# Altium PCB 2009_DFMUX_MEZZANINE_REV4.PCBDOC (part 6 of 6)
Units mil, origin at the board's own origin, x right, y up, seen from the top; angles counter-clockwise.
Board outline 4922.86 x 3627.76 mil, 6 copper layers (Top Layer, Internal Plane 1, Mid-Layer 1, Internal Plane 2, Mid-Layer 2, Bottom Layer); 519 components, 606 nets, 2175 pads, 757 vias.
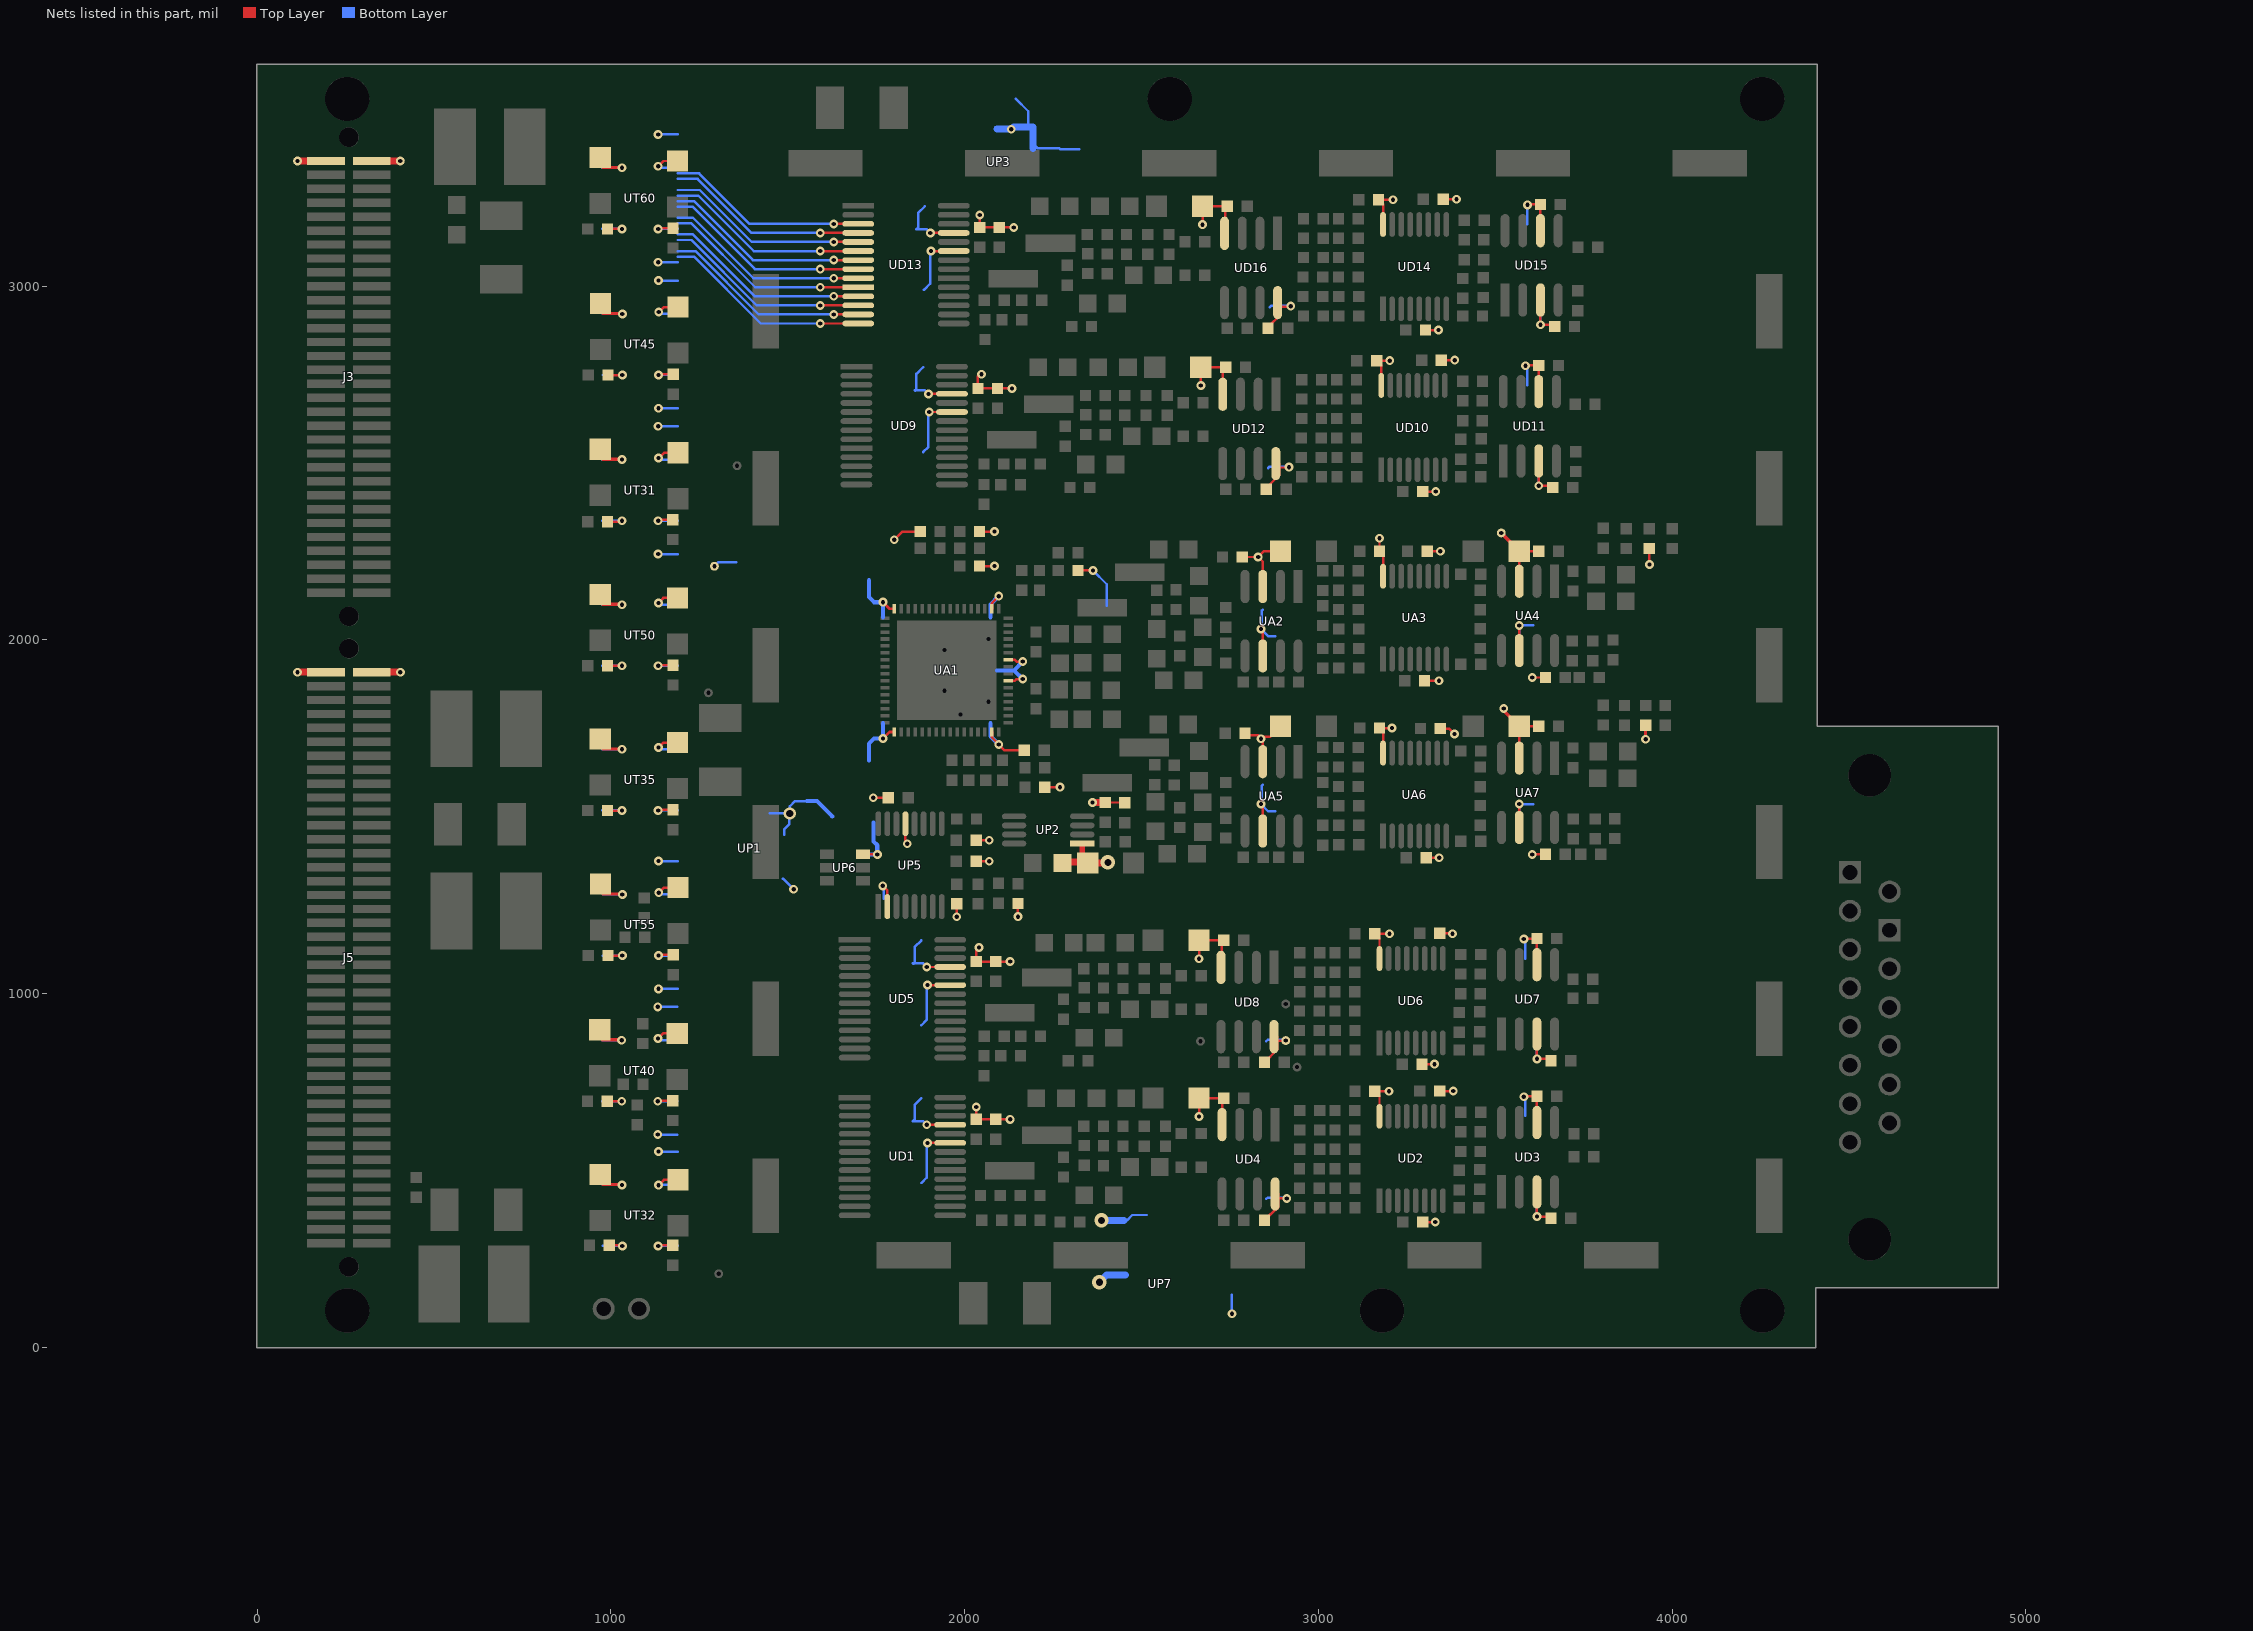
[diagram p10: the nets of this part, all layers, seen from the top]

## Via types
v1: diameter 25, hole 12, Top Layer to Bottom Layer, 692 vias
v2: diameter 40, hole 20, Top Layer to Bottom Layer, 39 vias
v3: diameter 35, hole 20, Top Layer to Bottom Layer, 23 vias
v4: diameter 22, hole 12, Top Layer to Bottom Layer, 3 vias

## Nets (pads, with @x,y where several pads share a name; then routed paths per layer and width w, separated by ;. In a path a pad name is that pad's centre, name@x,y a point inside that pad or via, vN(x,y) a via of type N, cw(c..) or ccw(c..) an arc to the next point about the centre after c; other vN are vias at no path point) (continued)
TRAN4_DATA4: UD13.3 UT60.8 | length 569.6
  Top Layer w7: v1(1630.1,3175.63) UD13.3@1699.03,3175.63
  Bottom Layer w7: UT60.8@1188.63,3318.47 1249.17,3318.47 1392,3175.63 v1(1630.1,3175.63)
TRAN4_DATA5: UD13.4 UT60.9 | length 576.4
  Top Layer w7: v1(1591.77,3150.03) UD13.4@1699.03,3150.03 UD13.4@1697.03,3148.17
  Bottom Layer w7: UT60.9@1188.63,3302.77 1244.87,3302.77 1397.6,3150.03 v1(1591.77,3150.03)
TRAN4_DATA6: UD13.5 UT60.11 | length 571.3
  Top Layer w7: v1(1630.1,3124.43) UD13.5@1699.03,3124.43
  Bottom Layer w7: UT60.11@1188.63,3271.37 1251.27,3271.37 1398.2,3124.43 v1(1630.1,3124.43)
TRAN4_DATA7: UD13.6 UT60.12 | length 575.4
  Top Layer w7: v1(1591.77,3098.83) UD13.6@1699.03,3098.83
  Bottom Layer w7: UT60.12@1188.63,3255.67 1246.97,3255.67 1403.8,3098.83 v1(1591.77,3098.83)
TRAN4_DATA8: UD13.7 UT60.13 | length 579.5
  Top Layer w7: v1(1630.1,3073.23) UD13.7@1699.03,3073.23
  Bottom Layer w7: UT60.13@1188.63,3239.97 1234.67,3239.97 1401.4,3073.23 v1(1630.1,3073.23)
TRAN4_DATA9: UD13.8 UT60.14 | length 583.6
  Top Layer w7: v1(1591.77,3047.63) UD13.8@1699.03,3047.63
  Bottom Layer w7: UT60.14@1188.63,3224.27 1230.37,3224.27 1407,3047.63 v1(1591.77,3047.63)
TRAN4_DATA10: UD13.9 UT60.16 | length 581.2
  Top Layer w7: v1(1630.1,3022.03) UD13.9@1699.03,3022.03
  Bottom Layer w7: UT60.16@1188.63,3192.87 1231.77,3192.87 1402.6,3022.03 v1(1630.1,3022.03)
TRAN4_DATA11: UD13.10 UT60.17 | length 585.3
  Top Layer w7: v1(1591.77,2996.43) UD13.10@1699.03,2996.43
  Bottom Layer w7: UT60.17@1188.63,3177.17 1227.47,3177.17 1408.2,2996.43 v1(1591.77,2996.43)
TRAN4_DATA12: UD13.11 UT60.19 | length 582.9
  Top Layer w7: v1(1630.1,2970.83) UD13.11@1699.03,2970.83
  Bottom Layer w7: UT60.19@1188.63,3145.77 1231.87,3145.77 1406.8,2970.83 v1(1630.1,2970.83)
TRAN4_DATA13: UD13.12 UT60.20 | length 587
  Top Layer w7: v1(1591.77,2945.23) UD13.12@1699.03,2945.23
  Bottom Layer w7: UT60.20@1188.63,3130.07 1227.57,3130.07 1412.4,2945.23 v1(1591.77,2945.23)
TRAN4_DATA14: UD13.13 UT60.22 | length 584.6
  Top Layer w7: v1(1630.1,2919.63) UD13.13@1699.03,2919.63
  Bottom Layer w7: UT60.22@1188.63,3098.67 1238.97,3098.67 1418,2919.63 v1(1630.1,2919.63)
TRAN4_DATA15: UD13.14 UT60.23 | length 588.7
  Top Layer w7: v1(1591.77,2894.03) UD13.14@1699.03,2894.03
  Bottom Layer w7: UT60.23@1188.63,3082.97 1234.67,3082.97 1423.6,2894.03 v1(1591.77,2894.03)
VCC3VP: CA4.1 CA15.1 CA18.1 CA27.1 CP8.2 CP10.1 CP19.2 DP2.1 RA9.2 RA44.2 RP9.1 RP11.2 RP31.1 UA1.7 UA1.10 UA1.18 UA1.63 UP2.1 UP5.2 | length 1203.7
  Top Layer w7: v1(1768.63,1304.37) 1781.53,1291.47 UP5.2@1781.53,1245.8 ; v1(1977.63,1217) RP31.1@1977.63,1253.37 ; v1(2096.5,1703.91) 2113.05,1687.37 CA27.1@2168.63,1687.37 ; UA1.7@2123.35,1884.11 2141.97,1884.11 2146.77,1888.91 v1(2164.27,1888.91) ; UA1.10@2123.35,1943.17 2141.97,1943.17 2146.77,1938.37 v1(2164.27,1938.37) ; RA44.2@2226.77,1583.37 v1(2269.27,1583.37) ; RP11.2@2276.63,1369 RP11.2@2279.63,1372 ; RA9.2@2320.27,2195.87 v1(2362.77,2195.87) ; CP10.1@2332.63,1371 CP10.1@2347.63,1369 CP10.1@2344.63,1372 ; CP8.2@2397.63,1540 2451.63,1540 RP9.1@2452.63,1539 ; v2(2404.63,1371) v2@2406.63,1369
  Top Layer w8: UA1.63@2077.09,1739.43 2077.09,1723.32 v1(2096.5,1703.91) ; UA1.18@2077.09,2087.85 2077.09,2103.95 v1(2096.5,2123.37)
  Top Layer w15: CP10.1@2332.63,1372 UP2.1@2332.63,1424
  Top Layer w20: RP11.2@2279.63,1372 CP10.1@2332.63,1372 ; CP10.1@2332.63,1371 CP10.1@2332.63,1372 ; CP10.1@2344.63,1372 CP10.1@2332.63,1372 ; CP10.1@2347.63,1369 v2@2406.63,1369 ; v1(2361.63,1540) CP8.2@2397.63,1540
  Bottom Layer w7: v1(1768.63,1304.37) 1771.63,1301.37 CP19.2@1771.63,1268.37 ; v1(2362.77,2195.87) 2401.63,2157 ; 2401.63,2157 DP2.1@2401.63,2096 2401.63,2157
  Bottom Layer w12: CA18.1@2073,1763.91 2073,1727.41 v1(2096.5,1703.91) ; CA4.1@2073,2063.37 2073,2099.87 v1(2096.5,2123.37) ; CA15.1@2091.77,1913.37 2139.81,1913.37 v1(2164.27,1888.91) ; 2139.27,1913.37 v1(2164.27,1938.37)
VCC5VN: CA16.1 CA17.2 CA32.1 CA34.2 CA38.1 CA39.2 CA42.1 CA43.2 CD1.1 CD2.2 CD8.1 CD9.1 CD14.2 CD15.1 CD21.1 CD22.2 CD28.1 CD29.1 CD34.2 CD35.1 CD41.1 CD42.2 CD48.1 CD49.1 CD54.2 CD55.1 CD61.1 CD62.2 CD68.1 CD69.1 CD74.2 CD75.1 CD83.1 CD85.1 CD87.1 CD89.1 CD91.2 CD93.2 CD95.2 CD97.2 CP16.2 DP4.2 RP20.2 RP22.1 UA2.6 UA4.6 UA5.6 UA7.6 UD1.23 UD3.6 UD4.4 UD5.23 UD7.6 UD8.4 UD9.23 UD11.6 UD12.4 UD13.23 UD15.6 UD16.4 UP7.3 | length 4074.5
  Top Layer w7: v1(1895.03,577.83) UD1.23@1959.03,577.83 ; v1(1895.03,1023.83) UD5.23@1959.03,1023.83 ; v1(1905.03,3098.83) UD13.23@1969.03,3098.83 ; RP22.1@2032.63,1433.37 v1(2069.63,1433.37) ; v1(2047.63,2750.37) 2042.57,2750.37 2037.63,2745.43 CD48.1@2037.63,2710.43 CD49.1@2092.63,2710.43 v1(2133.63,2710.43) ; v1(2128.63,644.43) CD9.1@2087.63,644.43 CD8.1@2032.63,644.43 ; v1(2128.63,1090.43) CD29.1@2087.63,1090.43 CD28.1@2032.63,1090.43 2032.63,1125.43 v1@2037.57,1130.37 ; v1(2138.63,3165.43) CD69.1@2097.63,3165.43 CD68.1@2042.63,3165.43 ; v1(2662.63,652.43) CD2.2@2662.63,704.43 CD1.1@2732.63,704.43 2728.63,700.43 2728.63,630.43 UD4.4@2727.63,629.43 ; v1(2662.63,1098.43) CD22.2@2662.63,1150.43 CD21.1@2732.63,1150.43 2726.63,1144.43 2726.63,1076 UD8.4@2724.63,1074 ; v1(2667.63,2718.43) CD42.2@2667.63,2770.43 CD41.1@2737.63,2770.43 2729.63,2762.43 UD12.4@2729.63,2694 ; v1(2672.63,3173.43) CD62.2@2672.63,3225.43 CD61.1@2742.63,3225.43 2736.63,3219.43 2736.63,3151 UD16.4@2734.63,3149 ; v1(2837.63,1535.43) 2839.63,1535.43 2842.63,1532.43 UA5.6@2842.63,1459.43 ; v1(2837.63,2030.43) 2839.63,2030.43 2842.63,2027.43 UA2.6@2842.63,1954.43 ; UA7.6@3567.63,1465.43 UA7.6@3567.63,1469.43 v1(3567.63,1535.43) v1@3567.63,1540.43 ; v1(3580.63,708.43) 3580.63,709.43 CD83.1@3617.63,709.43 UD3.6@3617.63,635.43 ; v1(3580.63,1154.43) 3580.63,1155.43 CD85.1@3617.63,1155.43 UD7.6@3617.63,1081.43 ; v1(3585.63,2774.43) 3585.63,2775.43 CD87.1@3622.63,2775.43 UD11.6@3622.63,2701.43 ; v1(3590.63,3229.43) 3590.63,3230.43 CD89.1@3627.63,3230.43 UD15.6@3627.63,3156.43 ; CD8.1@2032.63,644.43 v1(2032.63,679.43) CD8.1@2032.63,644.43 ; v1@2037.57,1130.37 v1(2040.63,1130.37) v1@2037.57,1130.37 ; CD68.1@2042.63,3165.43 v1(2042.63,3200.43) CD68.1@2042.63,3165.43 ; v1(1900.03,2643.83) UD9.23@1964.03,2643.83 v1(1900.03,2643.83) ; UA4.6@3567.63,1969.43 v1(3567.63,2040.43) UA4.6@3567.63,1969.43
  Bottom Layer w7: CD14.2@1877.63,464.43 1892.63,479.43 CD15.1@1892.63,534.43 1892.63,575.43 v1(1895.03,577.83) ; CD34.2@1877.63,910.43 1892.63,925.43 CD35.1@1892.63,980.43 1892.63,1021.43 v1(1895.03,1023.83) ; CD54.2@1882.63,2530.43 1897.63,2545.43 CD55.1@1897.63,2600.43 1897.63,2641.43 v1(1900.03,2643.83) ; CD74.2@1884.63,2989 1902.63,3007 CD75.1@1902.63,3055.43 1902.63,3096.43 v1(1905.03,3098.83) ; CP16.2@2449.63,359 2458.63,359 2473.63,374 RP20.2@2514.63,374 ; v1(2755.63,95) DP4.2@2755.63,149 ; CA34.2@2842.63,1590.43 2839.63,1587.43 2839.63,1537.43 v1(2837.63,1535.43) ; CA17.2@2842.63,2085.43 2839.63,2082.43 2839.63,2032.43 v1(2837.63,2030.43) ; CA32.1@2877.63,1515.43 2857.63,1515.43 ; CA16.1@2877.63,2010.43 2857.63,2010.43 ; CA43.2@3567.63,1465.43 v1(3567.63,1535.43) CA42.1@3606.63,1535.43 ; CA39.2@3567.63,1970.43 v1(3567.63,2040.43) CA38.1@3606.63,2040.43 ; v1@3580.63,709.43 v1(3580.63,708.43) 3579.63,708.43 3579.63,704 3584.63,699 CD91.2@3584.63,654 ; v1@3580.63,1155.43 v1(3580.63,1154.43) 3579.63,1154.43 3579.63,1149 3584.63,1144 CD93.2@3584.63,1099 ; v1@3585.63,2775.43 v1(3585.63,2774.43) 3589.2,2774.43 3589.63,2774 CD95.2@3589.63,2719 ; CD97.2@3589.63,3174 3589.63,3229.43 v1(3590.63,3229.43) ; v1(2837.63,1535.43) 2857.63,1515.43 ; v1(2837.63,1535.43) 2857.63,1515.43 ; v1(2837.63,2030.43) 2857.63,2010.43 ; v1(2837.63,2030.43) 2857.63,2010.43
  Bottom Layer w20: v2(2380.63,184) 2400.63,204 UP7.3@2454.63,204 ; v2(2386.63,359) CP16.2@2449.63,359
VCC5VP: CA3.1 CA5.1 CA23.1 CA24.1 CA36.1 CA37.1 CA40.1 CA41.1 CD3.1 CD4.2 CD6.1 CD19.1 CD20.1 CD23.1 CD24.2 CD26.1 CD39.1 CD40.1 CD43.1 CD44.2 CD46.1 CD59.1 CD60.1 CD63.1 CD64.2 CD66.1 CD79.1 CD80.1 CD81.1 CD82.1 CD84.1 CD86.1 CD88.1 CD90.1 CD92.1 CD94.1 CD96.1 CD98.1 CP11.1 CP14.1 DP3.1 pad.1@2907.63,867 pad.1@3517,2302 RA10.1 RA30.1 RA31.1 RA55.1 RD1.1 RD29.1 RD31.1 RD59.1 RD61.1 RD89.1 RD91.1 RD119.1 RP14.1 RP16.2 RP21.1 RP25.2 RP30.1 RP32.2 RP54.2 RP57.2 UA2.3 UA3.16 UA4.3 UA5.3 UA6.16 UA7.3 UD1.25 UD2.16 UD3.3 UD4.8 UD5.25 UD6.16 UD7.3 UD8.8 UD9.25 UD10.16 UD11.3 UD12.8 UD13.25 UD14.16 UD15.3 UD16.8 UP3.1 | length 6111.9
  Top Layer w7: v1(1893.03,629.03) UD1.25@1959.03,629.03 ; v1(1898.03,2695.03) UD9.25@1964.03,2695.03 ; v1(1903.03,3150.03) UD13.25@1969.03,3150.03 ; RP21.1@2032.63,1374 v1(2069.63,1374) ; CA5.1@2784.63,2234 v1(2829.63,2234) ; CA24.1@2792.63,1735.43 2797.63,1730.43 2828.63,1730.43 v1@2837.63,1721.43 ; v1(2837.63,1720.43) v1@2837.63,1721.43 ; UA2.3@2842.63,2150.43 2842.63,2221 v1(2829.63,2234) ; CD40.1@2847.63,805.43 2883.63,841.43 UD8.8@2883.63,868 ; CD80.1@2857.63,2880.43 2857.63,2884 2893.63,2920 UD16.8@2893.63,2943 ; CA23.1@2892.63,1755.43 2862.63,1725.43 2839.63,1725.43 2842.63,1722.43 v1@2842.63,1720.43 ; CA3.1@2892.63,2250.43 2846.07,2250.43 v1(2829.63,2234) ; pad.1@2907.63,867 2884.63,867 UD8.8@2883.63,868 ; v1(2916.63,2488) 2915.63,2487 2889.63,2487 UD12.8@2888.63,2488 ; v1(2921.63,2943) 2920.63,2942 2894.63,2942 UD16.8@2893.63,2943 ; UD2.16@3172.63,653.02 3172.63,711 CD6.1@3159.63,724 ; UD6.16@3172.63,1099.02 3172.63,1156 CD26.1@3159.63,1169 v1(3200.63,1169) ; UD10.16@3177.63,2719.02 3177.63,2776 CD46.1@3164.63,2789 ; UA6.16@3182.63,1679.68 3182.63,1740.43 CD82.1@3172.63,1750.43 v1(3208.2,1750.43) ; UA3.16@3182.63,2179.68 3182.63,2240.43 CD81.1@3172.63,2250.43 ; UD14.16@3182.63,3174.02 3182.63,3231 CD66.1@3169.63,3244 v1(3210.63,3244) ; RD29.1@3294.63,354 v1(3330.2,354) ; RA30.1@3299.63,1884 v1(3340.63,1884) ; v1@3340.63,1384.57 v1(3341.2,1384) ; RD91.1@3352.63,3245.43 v1(3390.2,3245.43) v1@3388.63,3247 ; UA7.3@3567.63,1665.43 CA40.1@3567.63,1755.43 CA41.1@3622.63,1755.43 ; UA4.3@3567.63,2165.43 CA36.1@3567.63,2250.43 CA37.1@3622.63,2250.43 ; UD3.3@3617.63,439.43 v1(3617.63,369.43) 3652.63,369.43 CD84.1@3657.63,364.43 ; UD7.3@3617.63,885.43 v1(3617.63,815.43) 3652.63,815.43 CD86.1@3657.63,810.43 ; UD11.3@3622.63,2505.43 v1(3622.63,2435.43) 3657.63,2435.43 CD88.1@3662.63,2430.43 ; UD15.3@3627.63,2960.43 v1(3627.63,2890.43) 3662.63,2890.43 CD90.1@3667.63,2885.43 ; v1@2837.63,1721.43 2837.63,1722.43 2839.63,1720.43 v1@2842.63,1720.43 ; v1@2842.63,1720.43 UA5.3@2842.63,1655.43 v1@2842.63,1720.43 ; CD20.1@2847.63,359.43 2883.63,395.43 UD4.8@2883.63,426.43 ; CD20.1@2847.63,359.43 UD4.8@2886.63,396.87 ; CD20.1@2847.63,359.43 UD4.8@2886.63,396.87 ; CD60.1@2852.63,2429 2888.63,2465 UD12.8@2888.63,2488 ; CD60.1@2852.63,2429 CD60.1@2852.63,2425.43 CD60.1@2852.63,2429 ; UD8.8@2874.63,878 UD8.8@2881.2,878 ; UD8.8@2874.63,878 UD8.8@2881.2,878 ; UD8.8@2874.63,878 2875.63,877 2875.63,876 UD8.8@2883.63,868 ; UD4.8@2877.63,433.43 2878.63,432.43 UD4.8@2878.63,431.43 ; UD4.8@2877.63,433.43 UD4.8@2884.2,433.43 ; UD4.8@2877.63,433.43 UD4.8@2884.2,433.43 ; UD4.8@2877.63,433.43 2877.63,432.43 UD4.8@2878.63,431.43 ; UD4.8@2878.63,431.43 UD4.8@2883.63,426.43 ; UD12.8@2879.63,2498 UD12.8@2880.63,2497 ; UD12.8@2879.63,2498 2879.63,2497 UD12.8@2880.63,2496 ; UD12.8@2879.63,2498 UD12.8@2880.63,2497 ; UD12.8@2879.63,2498 2886.2,2498 2887.63,2499.43 2887.63,2498.43 2888.63,2497.43 UD12.8@2888.63,2489 ; UD12.8@2880.63,2496 UD12.8@2880.63,2497 ; UD12.8@2880.63,2496 UD12.8@2888.63,2488 ; UD12.8@2880.63,2497 UD12.8@2888.63,2489 ; UD8.8@2881.2,878 UD8.8@2882.63,879.43 ; UD8.8@2882.63,879.43 2883.63,878.43 UD8.8@2883.63,877.43 ; UD8.8@2882.63,879.43 2882.63,878.43 UD8.8@2883.63,877.43 ; UD4.8@2883.63,426.43 UD4.8@2886.63,423.43 ; UD8.8@2883.63,868 UD8.8@2883.63,877.43 ; UD4.8@2884.2,433.43 2885.63,434.87 2886.63,433.87 UD4.8@2886.63,423.43 ; UD16.8@2884.63,2953 2884.63,2952 UD16.8@2893.63,2943 ; UD16.8@2884.63,2953 UD16.8@2893.63,2944 ; UD16.8@2884.63,2953 2891.2,2953 2892.63,2954.43 2892.63,2953.43 2893.63,2952.43 UD16.8@2893.63,2944 ; UD16.8@2884.63,2953 UD16.8@2893.63,2944 ; UD4.8@2886.63,396.87 UD4.8@2886.63,421 ; UD4.8@2886.63,421 UD4.8@2886.63,423.43 ; UD4.8@2886.63,421 2907.63,421 UD4.8@2886.63,421 ; UD12.8@2888.63,2488 UD12.8@2888.63,2489 ; UD16.8@2893.63,2943 UD16.8@2893.63,2944 ; CD6.1@3159.63,724 v1(3199.63,724) CD6.1@3159.63,724 ; CD46.1@3164.63,2789 v1(3201.63,2789) CD46.1@3164.63,2789 ; CD81.1@3172.63,2250.43 v1(3172.63,2287) CD81.1@3172.63,2250.43 ; RD59.1@3292.63,800.43 v1(3328.2,800.43) ; RD59.1@3292.63,800.43 v1(3328.2,800.43) ; RD59.1@3292.63,800.43 v1(3328.2,800.43) ; v1(3341.2,1384) RA55.1@3304.63,1384 v1(3341.2,1384) ; 3369.63,1749 v1(3384.63,1734) 3369.63,1749 ; 3369.63,1749 RA31.1@3344.63,1749 3369.63,1749 ; v1@3377.2,1170.43 v1(3378.63,1169) v1@3377.2,1170.43 ; v1@3377.2,1170.43 RD31.1@3342.63,1170.43 v1@3377.2,1170.43 ; v1(3385.2,2790.43) 3383.63,2792 v1(3385.2,2790.43) ; v1(3385.2,2790.43) RD61.1@3347.63,2790.43 v1(3385.2,2790.43) ; v1(1893.03,1075.03) UD5.25@1959.03,1075.03 v1(1893.03,1075.03) ; v1(2150.63,1217.37) RP30.1@2150.63,1254.37 v1(2150.63,1217.37) ; RD89.1@3294.63,2419 v1(3331.63,2419) RD89.1@3294.63,2419 ; RD119.1@3302.63,2875.43 v1(3339.63,2875.43) RD119.1@3302.63,2875.43 ; RA10.1@3307.63,2250.43 v1(3344.63,2250.43) RA10.1@3307.63,2250.43 ; RD1.1@3342.63,724.43 v1(3381.2,724.43) RD1.1@3342.63,724.43 ; v1(3604.63,1393.37) RP32.2@3641.63,1393.37 v1(3604.63,1393.37) ; v1(3604.63,1893.37) RP25.2@3641.63,1893.37 v1(3604.63,1893.37)
  Top Layer w8: v1(3925,1719) RP57.2@3925,1758 ; RP54.2@3935,2258 3935,2214 v1(3936,2213) v1@3936,2215
  Top Layer w10: pad.1@3517,2302 3567.63,2251.37 CA36.1@3567.63,2250.43 ; v1(3524,1806) 3524,1799.07 CA40.1@3567.63,1755.43
  Bottom Layer w7: CD3.1@1877.63,704.43 1858.63,685.43 1858.63,644.37 CD4.2@1853.63,639.37 1858.57,639.37 1858.63,639.43 1882.63,639.43 v1(1893.03,629.03) ; CD23.1@1877.63,1150.43 1858.63,1131.43 1858.63,1087 1857,1085.37 ; CD43.1@1882.63,2770.43 1863.63,2751.43 1863.63,2707 1862,2705.37 ; CD63.1@1887.63,3225.43 1868.63,3206.43 1868.63,3165.37 CD64.2@1863.63,3160.37 1868.57,3160.37 1868.63,3160.43 1892.63,3160.43 v1(1903.03,3150.03) ; v1(1893.03,1075.03) 1882.63,1085.43 1858.63,1085.43 1858.57,1085.37 1857,1085.37 ; v1(1898.03,2695.03) 1887.7,2705.37 1862,2705.37 ; RP16.2@2086.63,3449 2091.63,3444 ; v1(2131.63,3443) 2132.63,3444 v1@2137.63,3449 ; DP3.1@2144.63,3529 2179.63,3494 2179.63,3449 ; 2192.63,3404 2207.63,3389 CP11.1@2267.63,3389 2269.63,3387 RP14.1@2324.63,3387 ; CD19.1@2852.63,419.43 2856.63,423.43 2910.63,423.43 v1(2910.63,421) v1@2907.63,421 ; CD59.1@2857.63,2485.43 2861.63,2489.43 2915.63,2489.43 v1@2916.63,2488.43 ; CD79.1@2862.63,2940.43 2866.63,2944.43 2920.63,2944.43 v1@2921.63,2943.43 ; CD24.2@1855.63,1084 1855,1084 1853.63,1085.37 1857,1085.37 ; CD24.2@1855.63,1084 1857,1085.37 ; CD24.2@1855.63,1084 1857,1085.37 ; CD44.2@1860.63,2704 1860,2704 1858.63,2705.37 1862,2705.37 ; CD44.2@1860.63,2704 1862,2705.37 ; CD44.2@1860.63,2704 1862,2705.37 ; 2856.63,869.43 2910.63,869.43 pad.1@2910.63,867 ; 2856.63,869.43 CD39.1@2852.63,865.43 2856.63,869.43 ; pad.1@2910.63,867 pad.1@2907.63,867 pad.1@2910.63,867 ; v1@2916.63,2488.43 v1(2916.63,2488) v1@2916.63,2488.43 ; v1@2921.63,2943.43 v1(2921.63,2943) v1@2921.63,2943.43 ; v1(3617.63,369.43) CD92.1@3617.63,434.43 v1(3617.63,369.43) ; v1(3617.63,815.43) CD94.1@3617.63,880.43 v1(3617.63,815.43) ; v1(3622.63,2435.43) CD96.1@3622.63,2500.43 v1(3622.63,2435.43) ; v1(3627.63,2890.43) CD98.1@3627.63,2955.43 v1(3627.63,2890.43)
  Bottom Layer w20: 2091.63,3444 v1@2132.63,3444 ; v1@2137.63,3449 2179.63,3449 CP14.1@2192.63,3449 2192.63,3404 ; 2192.63,3404 UP3.1@2192.63,3389 2192.63,3404
VDD3V: CA7.2 CA25.1 CA44.1 CA45.1 CP4.2 CP7.1 CP21.1 CP22.2 CT27.1 CT28.2 CT31.1 CT32.2 CT33.1 CT34.2 CT37.1 CT38.2 CT41.1 CT42.2 CT45.1 CT46.2 CT49.1 CT50.2 CT53.1 CT54.2 DP1.1 pad.1@1292.63,2208 RA2.1 RA4.1 RA6.1 RA56.1 RP5.1 RP7.2 UA1.32 UA1.49 UP1.1 UP5.13 UP6.3 UT31.1 UT31.7 UT31.18 UT31.24 UT32.1 UT32.7 UT32.18 UT35.7 UT35.18 UT40.1 UT40.7 UT40.18 UT40.24 UT45.1 UT45.7 UT45.18 UT45.24 UT50.7 UT50.18 UT55.1 UT55.7 UT55.18 UT55.24 UT60.1 UT60.7 UT60.18 UT60.24 | length 5036.1
  Top Layer w7: v1@1132.63,872.37 1147.63,887.37 ; v1(1133.43,873.17) 1147.63,887.37 ; v1@1133.63,695.37 v1@1135.63,697.37 ; v1@1133.63,1694.37 1148.63,1709.37 ; v1(1133.63,3161.47) 1135.53,3163.37 CT54.2@1175.63,3163.37 ; v1@1134.43,3339.17 1148.63,3353.37 ; v1@1134.63,1517.37 v1@1136.63,1519.37 ; v1(1134.63,2748.47) 1136.53,2750.37 CT42.2@1176.63,2750.37 ; v1(1135.43,1285.17) 1149.63,1299.37 ; v1(1135.43,2926.17) 1149.63,2940.37 ; v1@1135.63,1107.37 v1@1137.63,1109.37 ; CT49.1@1189.63,1299.37 1149.63,1299.37 ; CT41.1@1189.63,2940.37 1149.63,2940.37 ; v1(1741.77,1553.37) RA56.1@1784.27,1553.37 ; v1(1801.13,2282.93) 1823.73,2305.87 RA6.1@1874.27,2305.87 ; UP5.13@1832.7,1480.05 1832.7,1428.3 v1(1837.63,1423.37) ; RA2.1@2041.77,2208.37 v1(2084.27,2208.37) ; RA4.1@2041.77,2305.87 v1(2084.27,2305.87) ; v1@1135.63,288.37 v1(1133.63,286.37) v1@1135.63,288.37 ; v1@1135.63,288.37 CT32.2@1174.63,288.37 v1@1135.63,288.37 ; v1@1135.63,697.37 CT38.2@1174.63,697.37 v1@1135.63,697.37 ; v1@1136.63,1519.37 CT34.2@1175.63,1519.37 v1@1136.63,1519.37 ; v1@1136.63,1928.37 CT46.2@1175.63,1928.37 v1@1136.63,1928.37 ; v1@1136.63,1928.37 1134.63,1926.37 v1@1136.63,1928.37 ; v1@1136.63,2339.37 1133.63,2336.37 v1@1136.63,2339.37 ; v1@1136.63,2339.37 CT28.2@1174.63,2339.37 v1@1136.63,2339.37 ; v1@1137.63,1109.37 CT50.2@1176.63,1109.37 v1@1137.63,1109.37 ; 1147.63,887.37 CT37.1@1187.63,887.37 1147.63,887.37 ; 1148.63,1709.37 v1(1134.43,1695.17) 1148.63,1709.37 ; 1148.63,1709.37 CT33.1@1188.63,1709.37 1148.63,1709.37 ; 1148.63,2118.37 v1(1134.43,2104.17) 1148.63,2118.37 ; 1148.63,2118.37 CT45.1@1188.63,2118.37 1148.63,2118.37 ; 1148.63,3353.37 CT53.1@1188.63,3353.37 1148.63,3353.37 ; 1149.63,473.37 CT31.1@1189.63,473.37 1149.63,473.37 ; 1149.63,473.37 v1(1134.63,458.37) 1149.63,473.37 ; 1149.63,1299.37 1134.63,1284.37 1149.63,1299.37 ; 1149.63,2940.37 1134.63,2925.37 1149.63,2940.37 ; 1150.63,2528.37 CT27.1@1189.63,2528.37 1150.63,2528.37 ; 1150.63,2528.37 1132.63,2510.37 1150.63,2528.37 ; UP6.3@1712.63,1393.37 v1(1753.27,1393.37) UP6.3@1712.63,1393.37
  Top Layer w8: v1(1769.27,1720.87) 1787.83,1739.43 UA1.49@1801.5,1739.43 ; v1(1769.27,2106.41) 1787.83,2087.85 UA1.32@1801.5,2087.85
  Bottom Layer w7: v1@1130.03,962.37 v1(1132.63,962.37) ; v1@1131.03,3428.37 v1(1133.63,3428.37) ; v1@1132.03,1374.37 v1(1134.63,1374.37) ; v1@1132.03,3015.37 v1(1134.63,3015.37) ; v1(1132.63,601.27) UT40.24@1187.63,601.27 ; v1@1132.63,2510.37 1133.83,2509.17 UT31.7@1188.63,2509.17 ; v1(1133.43,873.17) 1138.47,868.17 UT40.7@1187.63,868.17 ; v1(1133.63,286.37) 1133.73,286.47 UT32.18@1189.63,286.47 ; v1@1133.63,695.37 1133.73,695.47 UT40.18@1187.63,695.47 ; v1@1133.63,2103.37 v1(1134.43,2104.17) ; v1@1133.63,2336.37 1133.73,2336.47 UT31.18@1188.63,2336.47 ; v1(1133.63,3338.37) v1@1134.43,3339.17 ; v1(1134.43,1695.17) 1139.47,1690.17 UT35.7@1188.63,1690.17 ; v1(1134.43,2104.17) 1139.47,2099.17 UT50.7@1188.63,2099.17 ; v1@1134.47,3339.17 1139.47,3334.17 UT60.7@1188.63,3334.17 ; v1(1134.63,458.37) 1135.43,459.17 UT32.7@1189.63,459.17 ; v1@1134.63,1284.37 v1(1135.43,1285.17) ; v1@1134.63,1517.37 1134.73,1517.47 UT35.18@1188.63,1517.47 ; v1@1134.63,1926.37 1134.73,1926.47 UT50.18@1188.63,1926.47 ; v1@1134.63,2925.37 v1(1135.43,2926.17) ; v1(1135.43,1285.17) 1140.47,1280.17 UT55.7@1189.63,1280.17 ; v1(1135.43,2926.17) 1140.47,2921.17 UT45.7@1189.63,2921.17 ; v1@1135.63,1107.37 1135.73,1107.47 UT55.18@1189.63,1107.47 ; UT31.24@1188.63,2242.27 v1@1133.73,2242.27 ; pad.1@1292.63,2208 1303.63,2219 DP1.1@1354.63,2219 ; CP4.2@1485.63,1324 1487.63,1324 v1(1516.63,1295) ; UP1.1@1489.63,1449 1489.63,1464 1504.63,1479 v3@1504.63,1509 ; RP5.1@1554.63,1544 1520.63,1544 1505.63,1529 v3(1505.63,1509) ; v1(1132.63,962.37) UT40.1@1187.63,962.37 v1(1132.63,962.37) ; v1(1133.63,3161.47) UT60.18@1188.63,3161.47 ; v1(1133.63,3161.47) UT60.18@1188.63,3161.47 ; v1(1133.63,3161.47) UT60.18@1188.63,3161.47 ; v1(1133.63,3428.37) UT60.1@1188.63,3428.37 v1(1133.63,3428.37) ; v1@1133.73,2242.27 1133.63,2242.37 v1@1133.73,2242.27 ; v1(1134.63,1374.37) UT55.1@1189.63,1374.37 v1(1134.63,1374.37) ; v1(1134.63,2748.47) UT45.18@1189.63,2748.47 ; v1(1134.63,2748.47) UT45.18@1189.63,2748.47 ; v1(1134.63,2748.47) UT45.18@1189.63,2748.47 ; v1(1134.63,3015.37) UT45.1@1189.63,3015.37 v1(1134.63,3015.37) ; v3@1503.63,1509 v3@1504.63,1509 ; v3@1503.63,1509 RP7.2@1448.63,1509 v3@1503.63,1509 ; v3@1503.63,1509 1504.63,1510 v3(1505.63,1509) ; v3@1504.63,1509 v3(1505.63,1509) ; v1@1132.63,2603.37 UT31.1@1188.63,2603.37 v1@1132.63,2603.37 ; v1(1133.63,3067.27) UT60.24@1188.63,3067.27 v1(1133.63,3067.27) ; v1(1134.63,553.37) UT32.1@1189.63,553.37 v1(1134.63,553.37) ; v1(1134.63,1013.27) UT55.24@1189.63,1013.27 v1(1134.63,1013.27) ; v1(1134.63,2654.27) UT45.24@1189.63,2654.27 v1(1134.63,2654.27)
  Bottom Layer w12: RP5.1@1554.63,1544 1582.73,1544 CP7.1@1625.93,1500.8 ; CP22.2@1712.63,1393.37 v1(1753.27,1393.37) 1753.27,1419.37 1742.63,1430 CP21.1@1742.63,1483.37 ; CA45.1@1729.27,1658.91 1729.27,1706.41 1743.73,1720.87 v1(1769.27,1720.87) CA25.1@1769.27,1763.91 ; CA44.1@1729.27,2168.37 1729.27,2120.87 1743.73,2106.41 v1(1769.27,2106.41) CA7.2@1769.27,2063.37
  other v1: 1132.63,695.47 1134.63,1107.47 1133.63,1517.47 1133.63,1926.47 1133.63,2242.27 1133.63,2336.47 1134.43,2514.17 1133.63,2603.37
VDD_EXT: CT25.1 CT26.2 CT29.1 CT30.2 CT35.1 CT36.2 CT39.1 CT40.2 CT43.1 CT44.2 CT47.1 CT48.2 CT51.1 CT52.2 CT55.1 CT56.2 J3.1 J3.2 J5.1 J5.2 pad.1@114.33,3353.43 pad.1@404.85,3353.43 UT31.31 UT31.42 UT32.31 UT32.42 UT35.31 UT35.42 UT40.31 UT40.42 UT45.31 UT45.42 UT50.31 UT50.42 UT55.31 UT55.42 UT60.31 UT60.42 | length 3206.9
  Top Layer w7: CT55.1@969.63,3363.37 996.63,3336.37 v1@1026.75,3336.37 ; CT39.1@975.63,868.37 v1@1030.63,868.37 ; CT35.1@976.63,1690.37 v1(1031.63,1690.37) ; CT47.1@976.63,2099.37 v1@1031.63,2099.37 ; CT25.1@976.63,2509.37 v1(1031.63,2509.37) ; CT55.1@976.63,3334.37 v1(1031.63,3334.37) ; CT51.1@977.63,1280.37 v1@1032.63,1280.37 ; CT43.1@977.63,2921.37 v1@1032.63,2921.37 ; CT40.2@989.63,695.37 1030.63,695.37 v1(1030.63,695.67) ; CT36.2@990.63,1517.37 1031.63,1517.37 v1@1031.63,1517.67 ; CT48.2@990.63,1926.37 1031.63,1926.37 v1(1031.63,1926.67) ; CT26.2@990.63,2333.37 1028.33,2333.37 v1(1031.63,2336.67) ; CT56.2@990.63,3161.37 1031.63,3161.37 v1@1031.63,3161.67 ; CT52.2@991.63,1107.37 1032.63,1107.37 v1@1032.63,1107.67 ; CT44.2@991.63,2748.37 1032.63,2748.37 v1@1032.63,2748.67 ; v1@1032.63,459.37 v1@1031.63,459.37 ; CT39.1@995.63,870.37 v1@1025.75,870.37 ; CT39.1@995.63,870.37 CT39.1@968.63,897.37 CT39.1@995.63,870.37 ; CT35.1@996.63,1692.37 v1@1026.75,1692.37 ; CT35.1@996.63,1692.37 CT35.1@969.63,1719.37 CT35.1@996.63,1692.37 ; CT47.1@996.63,2101.37 v1@1026.75,2101.37 ; CT47.1@996.63,2101.37 CT47.1@969.63,2128.37 CT47.1@996.63,2101.37 ; CT25.1@996.63,2511.37 v1@1026.75,2511.37 ; CT25.1@996.63,2511.37 CT25.1@969.63,2538.37 CT25.1@996.63,2511.37 ; CT29.1@997.63,461.37 996.63,461.37 CT29.1@969.63,488.37 CT29.1@997.63,461.37 ; CT29.1@997.63,461.37 1029.63,461.37 v1@1031.63,459.37 ; CT51.1@997.63,1282.37 v1@1027.75,1282.37 ; CT51.1@997.63,1282.37 CT51.1@970.63,1309.37 CT51.1@997.63,1282.37 ; CT43.1@997.63,2923.37 v1@1027.75,2923.37 ; CT43.1@997.63,2923.37 CT43.1@970.63,2950.37 CT43.1@997.63,2923.37 ; v1@1025.75,870.37 1030.63,868.07 v1@1030.63,868.37 ; v1@1025.75,870.37 1028.63,870.37 v1@1030.63,868.37 ; v1@1026.75,1692.37 1031.63,1690.07 v1(1031.63,1690.37) ; v1@1026.75,1692.37 1029.63,1692.37 v1(1031.63,1690.37) ; v1@1026.75,2101.37 1031.63,2099.07 v1@1031.63,2099.37 ; v1@1026.75,2101.37 1029.63,2101.37 v1@1031.63,2099.37 ; v1@1026.75,2511.37 1031.63,2509.07 v1(1031.63,2509.37) ; v1@1026.75,2511.37 1029.63,2511.37 v1(1031.63,2509.37) ; v1@1026.75,3336.37 v1@1031.63,3334.07 ; v1@1026.75,3336.37 1029.63,3336.37 v1(1031.63,3334.37) ; v1@1027.75,1282.37 1032.63,1280.07 v1@1032.63,1280.37 ; v1@1027.75,1282.37 1030.63,1282.37 v1@1032.63,1280.37 ; v1@1027.75,2923.37 1032.63,2921.07 v1@1032.63,2921.37 ; v1@1027.75,2923.37 1030.63,2923.37 v1@1032.63,2921.37 ; v1@1031.63,459.37 977.63,459.37 v1@1031.63,459.37 ; v1@1031.63,3334.07 v1(1031.63,3334.37) ; v1@1031.63,3334.07 v1(1031.63,3334.37) ; v1@1032.63,286.67 1032.63,286.37 CT30.2@995.63,288.37 v1@1036.03,288.37 ; v1@1032.63,286.67 v1@1036.03,288.37 ; v1@1032.63,286.67 v1@1036.03,288.37
  Top Layer w20: v1(114.33,1908.37) J5.1@194.63,1908.37 ; pad.1@114.33,3353.43 J3.1@194.63,3353.43 ; J5.2@324.55,1908.37 v1(404.85,1908.37) ; J3.2@324.55,3353.43 pad.1@404.85,3353.43
  Bottom Layer w7: UT40.42@975.03,868.17 v1(1030.43,868.17) ; UT35.31@976.03,1517.47 v1(1031.43,1517.47) ; UT35.42@976.03,1690.17 v1@1031.43,1690.17 ; UT50.42@976.03,2099.17 v1(1031.43,2099.17) ; UT31.31@976.03,2336.47 v1@1031.43,2336.47 ; UT31.42@976.03,2509.17 v1@1031.43,2509.17 ; UT60.31@976.03,3161.47 v1(1031.43,3161.47) ; UT60.42@976.03,3334.17 1031.43,3334.17 v1(1031.63,3334.37) ; UT32.31@977.03,286.47 v1(1032.43,286.47) v1@1032.63,286.67 ; UT55.42@977.03,1280.17 v1(1032.43,1280.17) ; UT45.31@977.03,2748.47 v1(1032.43,2748.47) ; UT45.42@977.03,2921.17 v1(1032.43,2921.17) ; v1(1030.63,695.67) v1@1030.43,695.47 ; v1(1031.63,1926.67) v1@1031.43,1926.47 ; v1@1032.63,1107.67 v1(1032.43,1107.47) ; v1@1030.43,695.47 UT40.31@975.03,695.47 v1@1030.43,695.47 ; v1(1030.43,868.17) 1030.63,868.37 v1(1030.43,868.17) ; v1(1031.43,459.17) v1@1032.43,459.17 ; v1(1031.43,459.17) UT32.42@977.03,459.17 v1(1031.43,459.17) ; v1(1031.43,459.17) 1031.63,459.37 v1@1032.63,459.37 ; v1(1031.43,1517.47) 1031.63,1517.67 v1(1031.43,1517.47) ; v1@1031.43,1690.17 v1(1031.63,1690.37) v1@1031.43,1690.17 ; v1@1031.43,1926.47 UT50.31@976.03,1926.47 v1@1031.43,1926.47 ; v1(1031.43,2099.17) 1031.63,2099.37 v1(1031.43,2099.17) ; v1@1031.43,2336.47 v1(1031.63,2336.67) v1@1031.43,2336.47 ; v1@1031.43,2509.17 v1(1031.63,2509.37) v1@1031.43,2509.17 ; v1(1031.43,3161.47) 1031.63,3161.67 v1(1031.43,3161.47) ; v1@1032.43,459.17 v1@1032.63,459.37 ; v1@1032.43,459.17 v1@1032.63,459.37 ; v1(1032.43,1107.47) UT55.31@977.03,1107.47 v1(1032.43,1107.47) ; v1(1032.43,1280.17) 1032.63,1280.37 v1(1032.43,1280.17) ; v1(1032.43,2748.47) 1032.63,2748.67 v1(1032.43,2748.47) ; v1(1032.43,2921.17) 1032.63,2921.37 v1(1032.43,2921.17)
VREF_IN: 
VREF_IN_5370: 
VREF_OUT: 
VREF_OUT_6270: 
pads on no net: J3.41 J3.42 J3.49 J3.HOLE1 J3.HOLE2 J4.4 J4.5 J4.Hole29 J4.Hole30 J5.18 J5.23 J5.73 J5.HOLE1 J5.HOLE2 J6.12 J6.13 J6.14 J6.15 J6.16 J6.17 J6.18 MH1.1 MH2.1 MH3.1 MH4.1 MH5.1 MH6.1 RD30.2 RD50.2 RD80.2 RD120.2 UA2.7 UA4.7 UA5.7 UA7.7 UD3.7 UD7.7 UD11.7 UD15.7 UP1.6 UP1.7 UP2.6 UP2.7 UP3.6 UP3.7 UP5.8 UP7.2 UT31.16 UT32.4 UT32.9 UT32.11 UT32.12 UT32.26 UT32.27 UT32.29 UT32.30 UT32.32 UT32.33 UT32.35 UT35.23 UT50.23 UT70.9 UT72.9 UT73.7 UT73.8 UT73.9 UT73.10

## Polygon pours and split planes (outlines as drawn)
N1002964 on Top Layer "Top Layer-N1002964" (hatched Horizontal grid 7.5 track 8, remove dead copper, pour order 1000): 419.63,3554 519.63,3554 519.63,3384 419.63,3384
N192153 on Top Layer "Top Layer-N192153" (hatched Horizontal grid 7.5 track 8, pour order 1001): 754.63,3584 914.63,3584 914.63,3449 754.63,3449
N193110 on Mid-Layer 1 "Mid-Layer 1-N193110" (hatched Horizontal grid 7.5 track 8, remove dead copper, pour order 1002): 794.63,1594 939.63,1449 1344.63,1449 1344.63,1514 1229.63,1629 944.63,1629 944.63,1799 899.63,1844 629.63,1844 609.63,1824 609.63,1774 639.63,1744 644.63,1744
VCC3VP on Mid-Layer 1 "Mid-Layer 1-VCC3VP" (hatched Horizontal grid 7.5 track 8, remove dead copper, pour order 1003): 1739.63,1334 1859.63,1334 1909.63,1384 1909.63,1894 2049.63,2034 2049.63,2134 2124.63,2209 2401.77,2208.37 2454.27,2155.87 2454.63,1344 2299.63,1189 1804.63,1189 1739.63,1254
N192153 on Mid-Layer 1 "Mid-Layer 1-N192153" (hatched Horizontal grid 7.5 track 8, remove dead copper, pour order 1004): 829.63,3579 2039.63,3579 2039.63,3459 829.63,3459
N1002964 on Mid-Layer 2 "Mid-Layer 2-N1002964" (hatched Horizontal grid 7.5 track 8, remove dead copper, pour order 1005): 54.63,499 169.63,499 169.63,3314 344.63,3489 419.63,3489 419.63,3544 524.63,3544 524.63,3389 389.63,3389 339.63,3339 339.63,384 54.63,384
N570816 on Mid-Layer 2 "Mid-Layer 2-N570816" (hatched Horizontal grid 7.5 track 8, remove dead copper, pour order 1006): 599.63,1269 2099.63,1269 2099.63,1434 2194.63,1434 2194.63,1179 1304.63,1179 1294.63,1169 599.63,1169
VCC5VN on Mid-Layer 2 "Mid-Layer 2-VCC5VN" (hatched Horizontal grid 7.5 track 8, remove dead copper, pour order 1007): 1842.63,3629 3849.63,3629 3849.63,-1 1677.63,-1 1677.63,252 1722.63,297 1746.63,297 1760.63,311 1760.63,360 1715.63,405 1715.63,507 1744.63,536 1761.63,536 1781.63,556 1781.63,584 1759.63,606 1736.63,606 1718.63,624 1718.63,712 1764.63,758 1764.63,800 1723.63,841 1723.63,951 1779.63,1007 1779.63,1028 1781.63,1030 1758.63,1053 1742.63,1053 1726.63,1069 1726.63,1155.88 1746.63,1175.88 1816.63,1175.88 1828.63,1165 2206.63,1165 2206.63,1444 2092.63,1444 2092.63,1276 1829.63,1276 1829.63,1334 1829.27,1355.87 1976.77,1503.37 1976.77,2188.37 1842.63,2323
no net on Top Overlay (hatched 90Degree grid 7.5 track 8, remove dead copper): 12.5,3345 12.5,3360 45,3360 45,3380 85,3352.5 45,3325 45,3345
no net on Top Overlay (hatched 90Degree grid 7.5 track 8, remove dead copper): 15,1900 15,1915 47.5,1915 47.5,1935 87.5,1907.5 47.5,1880 47.5,1900
no net on Top Overlay (hatched 90Degree grid 7.5 track 8, remove dead copper): 4345,1335 4345,1350 4377.5,1350 4377.5,1370 4417.5,1342.5 4377.5,1315 4377.5,1335
no net on Top Paste (hatched Horizontal grid 2 track 2): 1865,1769 2040,1769 2040,1819 2090,1819 2090,2024 1865,2024
no net on Top Solder (hatched Horizontal grid 2 track 2): 1865,1769 2040,1769 2040,1819 2090,1819 2090,2024 1865,2024
GND_SIGNAL on Internal Plane 1 (split plane): 4389.98,1755.02 4390.37,1751.09 4391.51,1747.32 4393.37,1743.85 4395.87,1740.8 4398.92,1738.31 4402.39,1736.45 4406.16,1735.3 4410.08,1734.92 4901.75,1734.92 4901.75,188.08 4406.02,188.08 4402.09,187.7 4398.32,186.55 4394.85,184.69 4391.8,182.2 4389.31,179.15 4387.45,175.68 4386.3,171.91 4385.92,167.98 4385.92,19.08 19.08,19.08 19.08,3606.65 4389.98,3606.65
VCC5VP on Internal Plane 2 (split plane): 534 vertices, not listed, extent 1079.81,19.08 4901.75,3606.65
VDD_EXT on Internal Plane 2 (split plane): 1061.46,173.18 868.81,173.18 868.81,254 868.5,255.56 867.62,256.88 866.29,257.77 864.73,258.08 863.46,257.83 863.71,259.1 863.4,260.66 862.52,261.98 861.19,262.87 859.63,263.18 754.63,263.18 753.07,262.87 751.75,261.98 750.87,260.66 750.55,259.1 750.81,257.83 749.54,258.08 747.97,257.77 746.65,256.88 745.77,255.56 745.46,254 745.46,19.08 19.08,19.08 19.08,3606.65 1061.46,3606.65
N95032 on Internal Plane 2 (split plane): 850.46,164 850.77,162.44 851.65,161.12 852.97,160.23 854.54,159.92 855.81,160.17 855.55,158.9 855.87,157.34 856.75,156.02 858.07,155.13 859.63,154.82 1066.69,154.82 1067.15,154.92 1067.75,154.02 1069.07,153.13 1070.63,152.82 1650.46,152.82 1650.46,149 1650.77,147.44 1651.65,146.12 1652.97,145.23 1654.54,144.92 1655.81,145.17 1655.55,143.9 1655.87,142.34 1656.75,141.02 1658.07,140.13 1659.63,139.82 2640.46,139.82 2640.46,19.08 763.81,19.08 763.81,244.82 850.46,244.82
VDD_EXT on Internal Plane 2 (split plane): 1660.65,154.1 1659.63,154.1 1658.61,153.9 1658.61,156.9 1659.63,156.9 1660.65,157.1

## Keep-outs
Keep-Out Layer:
  lines w50: 0,0 0,3625.73 4409.07,3625.73 4409.07,1814.87 4410,1754 4920.83,1754 4920.83,169 4405,169 4405,-1 0,0
  text "KEEPOUT" at 2010,-1917.5 h100

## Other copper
Top Layer:
  rectangle net N1002964: 486.58,3381.5 522.13,3515.87
  rectangle net N192153: 754.92,3445.87 829.63,3513.13
  text "Board Dim: 92mm x 125mm" at 4861.62,436.7 h30 r90
  text "L1 (TOP) .GTL" at 434.63,-686.63 h100
Mid-Layer 1:
  text "VCC3V Analog" at 2264.62,3694 h37.5 r90
  text "L3 (ML1) .G1" at 434.63,-1086.63 h100
Mid-Layer 2:
  text "L5 (ML2) .G2" at 409.63,-1286.63 h100
Bottom Layer:
  text "L6 (BOT) .GBL" at 1319.63,-1714.13 h100
Internal Plane 1 (plane layer: these items are gaps in the copper):
  lines w0.03: 989.63,3629 1737.03,3629
  lines w10: -486.8,4.07 -261.8,4.07 ; -486.8,3625.73 -261.8,3625.73 ; -393.05,60.32 -374.3,4.07 ; -393.05,3569.48 -374.3,3625.73 ; -374.3,1626.98 -374.3,4.07 ; -374.3,2002.82 -374.3,3625.73 ; -355.55,60.32 -374.3,4.07 ; -355.55,3569.48 -374.3,3625.73 ; 0,-629.63 0,-404.63 ; 0,-348.47 0,-123.47 ; 56.25,-535.88 0,-517.13 ; 56.25,-498.38 0,-517.13 ; 56.25,-254.72 0,-235.97 ; 56.25,-217.22 0,-235.97 ; 993.63,3629 0,3629 0,-1 1029.63,-1 1679.63,-1 ; 1752.72,2830 1979.63,2831 2031.63,2779 2076.63,2779 2121.63,2824 3874.63,2824 4122.63,2576 4122.63,1759 4237.63,1644 4275,1644 ; 1764.63,764 1989.63,764 2019.63,734 2034.63,704 2099.63,704 2154.63,759 4167.63,759 4254.63,672 4280,672 ; 1784,1348.37 1879,1348.37 1962.13,1431.5 1962.13,1756.5 1893.63,1825 1893.63,2000.43 2028.13,2132.5 2053.63,2132.93 2125,2204.3 2125,2343 ; 1785.63,2343 2125,2343 ; 1962.13,1529 2179.63,1529 2197.63,1547 2293.63,1547 2318.63,1572 2480,1572 2490,1562 2490,1469 2530,1429 2530,1409 2600,1339 3840,1339 3906.63,1273 4176.63,1003 4176.63,869 4276.63,769 ; 2014.58,-235.97 0,-235.97 ; 2276.67,-517.13 0,-517.13 ; 2390.42,-235.97 4405,-235.97 ; 2495,1891 2550,1836 4000,1836 4000,1549 4115,1434 4115,1369 4285,1199 ; 2644.17,-517.13 4920.83,-517.13 ; 4261.63,1289 4201.63,1349 4201.63,1530 4046.63,1685 4046.63,2299 4001.63,2344 3835,2344 3850.63,2343 2125,2343 ; 4348.75,-254.72 4405,-235.97 ; 4348.75,-217.22 4405,-235.97 ; 4405,-348.47 4405,-123.47 ; 4864.58,-535.88 4920.83,-517.13 ; 4864.58,-498.38 4920.83,-517.13 ; 4920.83,-629.63 4920.83,-404.63 ; 5191.37,-1 5416.37,-1 ; 5191.37,1754 5416.37,1754 ; 5285.12,55.25 5303.87,-1 ; 5285.12,1697.75 5303.87,1754 ; 5287,169 5512,169 ; 5287,1754 5512,1754 ; 5303.87,696.92 5303.87,-1 ; 5303.87,1056.08 5303.87,1754 ; 5322.62,55.25 5303.87,-1 ; 5322.62,1697.75 5303.87,1754 ; 5380.75,225.25 5399.5,169 ; 5380.75,1697.75 5399.5,1754 ; 5399.5,781.92 5399.5,169 ; 5399.5,1141.08 5399.5,1754 ; 5418.25,225.25 5399.5,169 ; 5418.25,1697.75 5399.5,1754
  text "External Dirty GND" at 314.65,3689 h37.5 r90
  text "Digital GND" at 1349.65,3689 h37.5 r90
  text "Analog GND" at 2919.62,3689 h37.5 r90
  text "3622m" at -324.3,1683.23 h56.25 r90
  text "1585m" at 5349.5,1084.83 h56.25 r270
  text "1755m" at 5253.87,999.83 h56.25 r270
  text "4405m" at 2070.83,-285.97 h56.25
  text "4921m" at 2332.92,-567.13 h56.25
  text "L2 (GND) .GP1" at 402.13,-876.63 h100
Internal Plane 2 (plane layer: these items are gaps in the copper):
  lines w10: 1659.63,149 2649.63,149 2649.63,-1 754.63,-1 754.63,254 859.63,254 859.63,164 1659.63,164 ; 1659.63,162 1070.63,162 1070.63,3629 1735.63,3629 ; 1679.63,149 2654.63,149 2654.63,-1 4402.5,-1 4402.5,170 4922.63,170 4922.63,1755 4407.5,1755 4407.5,3629 1736.63,3629 ; 1774.63,1344 1879.63,1349 ; 1804.63,1349 1879.63,1349 ; 1962.5,1757.5 1961.94,1431.31 1879.63,1349
  text "VCC5p Analog" at 2780,3552.5 h37.5
  text "VDD3V Digital" at 1152.5,3545 h37.5
  text "L4 (PWR) .GP2" at 402.13,-1496.63 h100

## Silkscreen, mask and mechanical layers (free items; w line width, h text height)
Top Overlay:
  circle w12: c1709.63,1253.37 r6
  lines w5: 1479.63,991.37 1479.63,1583.37 ; 1397.63,219 4317.63,219 4317.63,3394 1397.63,3394 1397.63,219 ; 1482.63,304 4232.63,304 4232.63,3304 1482.63,3304 1482.63,304
  lines w6: 1695.63,1524 1720.63,1524 1738.63,1506 ; 2012.5,1562.5 2012.5,1580 ; 2075,1577.5 2082.5,1570 2082.5,1552.5
  lines w10: 1305.09,4347.47 ccw(c1353.5,4387) 1305.21,4347.33
  text "+6V" at 424.62,3548.98 h40
  text "McGill Digital fMUX Mezzanine" at 2684.63,3530.87 h45
  text "Rev 4 - Made in CANADA - Dec 2009" at 2681.05,3456.23 h33.75
  text "Matt Dobbs <Matt.Dobbs@McGill.ca>, George Zizka" at 2685.05,3400.73 h30
  text "Comb4" at 3899.63,3069 h37.5
  text "Carrier" at 3854.63,2999 h37.5
  text "Comb3" at 3864.63,2619 h37.5
  text "Nuller" at 3849.63,2554 h37.5
  text "Module B" at 4219.63,2384 h75 r90
  text "DemodB" at 3924.63,2004 h37.5
  text "+4V" at 509.62,1938.98 h30
  text "DemodA" at 3915,1480 h37.5
  text "Comb2" at 3849.63,984 h37.5
  text "Nuller" at 3849.63,924 h37.5
  text "Module A" at 4214.63,729 h75 r90
  text "Mount DB15f this side" at 4779.65,585.67 h30 r90
  text "Comb1" at 3869.63,494 h37.5
  text "Carrier" at 3829.63,434 h37.5
  text "____" at 16.28,246.22 h30 r90
  text "____" at 16.28,246.22 h30 r90
  text "GND" at 84.63,243.37 h40 r90
  text "-6V" at 332.13,58.37 h40
  text "EXT_GND" at 775,15 h35
  text "DIG_GND" at 1070,15 h35
  text "TOP IDENT (.GTO)" at 2394.63,-714.13 h100
Bottom Overlay:
  text "VCC5VP" at 2087.5,3546.5 h37.5
  text "Rev 4 - Made in CANADA - Dec 2009" at 4103.25,3409.38 h75 r90
  text "Copyright 2009" at 4348.67,3409.38 h75 r90
  text "Matt Dobbs <Matt.Dobbs@McGill.ca>, George Zizka" at 4210.92,3407.38 h56.25 r90
  text "McGill Digital fMUX Mezzanine" at 3962.67,3406.38 h75 r90
  text "TP" at 2925,3164 h30
  text "TP" at 2280,3109 h30
  text "Carrier" at 3836.72,3089 h37.5
  text "TP" at 2215,2999 h30
  text "Module B" at 3035.3,2845.83 h75 r90
  text "TP" at 2760,2809 h30
  text "TP" at 2910,2704 h30
  text "TP" at 2270,2649 h30
  text "Nuller" at 3847.95,2639 h37.5
  text "TP" at 2215,2549 h30
  text "TP" at 2755,2354 h30
  text "VDD3V" at 1462.5,2251.5 h37.5 r270
  text "TP" at 2710,2159 h30
  text "TP" at 3535,2154 h30
  text "Demod" at 3789.62,2134 h37.5
  text "TP" at 2750,1979 h30
  text "VCC3VP" at 2492.5,1866.5 h37.5 r270
  text "TP" at 3480,1829 h30
  text "TP" at 2710,1664 h30
  text "TP" at 3535,1659 h30
  text "Demod" at 3784.62,1639 h37.5
  text "TP" at 2775,1459 h30
  text "1" at 4472.97,1423.43 h30 r270
  text "TP" at 3485,1329 h30
  text "Module A" at 3032.8,1303.33 h75 r90
  text "TP" at 2900,1084 h30
  text "TP" at 2225,1029 h30
  text "Nuller" at 3790.3,1000.83 h37.5
  text "TP" at 2255,919 h30
  text "TP" at 2755,744 h30
  text "TP" at 2905,644 h30
  text "TP" at 2255,584 h30
  text "Carrier" at 3797.8,548.33 h37.5
  text "TP" at 2215,479 h30
  text "____" at 16.28,451.22 h30 r90
  text "____" at 16.28,451.22 h30 r90
  text "TP" at 2700,284 h30
  text "____" at 16.28,246.22 h30 r90
  text "LED AUX" at 1369.63,163.37 h37.5 r270
  text "VCC5VN" at 3016.57,53.07 h37.5
  text "BOTTOM IDENT (.GBO)" at 3902.13,-896.63 h100
Top Paste:
  text "TOP SOLDER PASTE (.GTP)" at 2402.13,-1316.63 h100
Bottom Paste:
  text "BOTTOM SOLDER PASTE (.GBP)" at 4542.13,-1716.63 h100
Top Solder:
  text "TOP SOLDER MASK (.GTS)" at 2382.13,-1096.63 h100
Bottom Solder:
  text "BOTTOM SOLDER MASK (.GBS)" at 4522.13,-1516.63 h100
Mechanical 1:
  lines w2: 4869.63,0 4920.83,0 4920.83,56.5 ; 4869.63,3625.73 4920.83,3625.73 4920.83,3579 ; 0,0 4405,0 4405,169 4920.83,169 4920.83,1754 4409.07,1754 4409.07,3625.73 0,3625.73 0,0
  text "McGill: DfMux Mezzanine Board  Rev4" at 467.5,4722.5 h100
  text "Nominal Size: 4.920 x 3.625 inches" at 543,4454 h100
  text "FINISHED BOARD: 0.062\" (Nom)  370HR" at 488,4196.5 h100
  text "ARRANGE LAYERS SEQUENTIALLY: L1-L6" at 528,3986.5 h100
  text "Thieving Copper Dots CAN be added to INNER layers if needed" at 8,3806.5 h80
  text "BOARD OUTLINE" at 412.5,-1912.5 h100
Drill Drawing:
  lines w5: 5620.93,3481.35 7471.32,3481.35
  lines w20: 5274.67,3139.5 5786.48,3139.5 ; 5287.17,3377 5798.98,3377 ; 5294.67,2852.5 5806.48,2852.5 ; 5297.17,2519.5 5808.98,2519.5 ; 5304.67,2064.5 5816.48,2064.5 ; 5305.57,2284.71 5817.38,2284.71
  text "370HR : 6 Layer PCB, Approximate Build:" at 4705,3562.5 h80
  text "TopLayer :0.5oz Plus Plating" at 5865.22,3363.24 h60
  text "L1" at 5105,3340 h80
  text "4.0 mils spacing" at 5708.11,3236.66 h60
  text "Plane 1: 1oz" at 5853.05,3114.2 h60
  text "L2" at 5107.5,3105 h80
  text "5.0 mils spacing" at 5708.11,2986.66 h60
  text "MidLayer1: 1/2oz" at 5844.76,2820.03 h60
  text "L3" at 5090,2817.5 h80
  text "Excess Material" at 5392.5,2635 h60
  text "MidLayer4: 1/2oz" at 5847.26,2487.03 h60
  text "L4" at 5102.5,2482.5 h80
  text "5.0 mils spacing" at 5730,2372.5 h60
  text "L5" at 5122.5,2252.5 h80
  text "Plane 2 : 1oz" at 5896.12,2245.34 h60
  text "4.0 mils spacing" at 5705,2152.5 h60
  text "Bottom Layer :0.5oz Plus Plating" at 5889.49,2045.38 h60
  text "L6" at 5122.5,2030 h80
  text "Total thickness = .093" at 5365.22,1905.57 h60
  text "ALL ROUTED LAYERS:" at 5515,1732.5 h60
  text "7 mils = 50 OHMS" at 5587.5,1612.5 h60
  text "FINISHED HOLE SIZES" at 5385,1382.5 h100
  text ".Legend" at 5172.13,-121.63 h100 r90
  text "DRILL DRAWING (.GD1)" at 2880,-1922.5 h100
